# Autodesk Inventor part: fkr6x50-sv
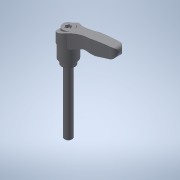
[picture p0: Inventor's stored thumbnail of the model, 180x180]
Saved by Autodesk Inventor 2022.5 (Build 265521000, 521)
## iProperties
Created: 2017-09
Part Number: fkr6x50-sv
Material: 一般
Document SubType Name: Modeling
Designer: imaocorp
Density: 1 g/cm^3
Appearance: 既定
Author: imaocorp
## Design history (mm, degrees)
node "fkr6x50-sv.x_t1"
node "fkr6x50-sv"
node "Base1"
